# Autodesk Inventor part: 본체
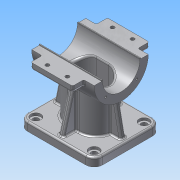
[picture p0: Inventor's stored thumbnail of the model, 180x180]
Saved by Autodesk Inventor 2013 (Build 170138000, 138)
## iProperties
Created: 2015-12
Part Number: 본체
Material: 알루미늄 6061
Document SubType Name: Modeling
Designer: mduedu
Density: 2.71 g/cm^3
Mass: 475.397 g
Surface Area: 479.254 cm^2
Volume: 175.423 cm^3
Author: mduedu
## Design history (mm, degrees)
sketch "스케치1"
  geometry: L1 (45, 40)-(-45, 40); L2 (-45, 40)-(-45, -40); L3 (-45, -40)-(45, -40); L4 (45, -40)-(45, 40); L5 (45, 40)-(-45, -40); L6 (-45, 40)-(45, -40); 1 further point
  constraints: 12 end point, 2 midpoint, 2 parallel, 1 horizontal, 1 perpendicular
  dimensions: "d0" = 90 distance of L2.end L3.end; "d2" = 80 distance of L1.end L2.end
extrude "돌출1" new body sketch "스케치1" distance "d3" = 10; taper "d4" = 0 deg
sketch "스케치2"
  geometry: L1 (0, 40)-(0, -40) reference; C1 r 32.5 at (80, 0); 1 further point
  constraints: 1 centre point
  dimensions: "d5" = 65 diameter of C1; "d6" = 80 distance from line of C1.centre L1
extrude "돌출2" join sketch "스케치2" stored distance "d7" = 75; taper "d8" = 0 deg
sketch "스케치3"
  geometry: L1 (-27.5, -20)-(27.5, -20); L2 (27.5, -20)-(27.5, 20); L3 (27.5, 20)-(-27.5, 20); L4 (-27.5, 20)-(-27.5, -20); L5 (-27.5, -20)-(27.5, 20); L6 (27.5, -20)-(-27.5, 20); 1 further point
  constraints: 12 end point, 2 midpoint, 2 parallel, 1 horizontal, 1 perpendicular
  dimensions: "d9" = 55 distance of L2.end L3.end; "d11" = 40 distance of L1.end L2.end
extrude "돌출3" new body sketch "스케치3" stored distance "d12" = 75; taper "d13" = 0 deg
fillet "모깎기1"
fillet "모깎기2"
feature "결합1"
  node "솔리드2"
fillet "모깎기3" dims "d14" = 10
sketch "스케치4"
  geometry: L1 (-37.5, 47.5)-(37.5, 47.5) reference; L2 (35, 10)-(45, 10) reference; L3 (32.5, 47.5)-(40, 10); L4 (37.5, 47.5)-(37.5, 112.5) reference; L5 (45, 10)-(45, 0) reference; 1 further point
  constraints: 2 end point, 1 midpoint, 1 point on line
  dimensions: "d15" = 5 distance from line of L3.start L4; "d16" = 5 distance from line of L3.end L5
sketch "스케치5"
  geometry: L1 (10, 40)-(10, 30) reference; L2 (10, 35)-(56.569, 22.522); L3 (0, 40)-(10, 40) reference; 2 further points
  constraints: 2 end point, 1 midpoint, 2 other
  dimensions: "d17" = 5 distance from line of L2.start L3; "d18" = 15 deg angle of L2 L3
feature "리브1" dims "d19" = 1, "d20" = 6, "d21" = 0, "d22" = 0, "d23" = 1, "d24" = 1
feature "리브2" dims "d25" = 1, "d26" = 6, "d27" = 0, "d28" = 0, "d29" = 1, "d30" = 1
fillet "모깎기4" dims "d31" = 2
fillet "모깎기5" dims "d32" = 2
fillet "모깎기6" dims "d33" = 2
sketch "스케치6"
  geometry: A1 r 10 centre (-35, 30) between (-35, 40) and (-45, 30) reference; A2 r 10 centre (35, 30) between (45, 30) and (35, 40) reference; A3 r 10 centre (35, -30) between (35, -40) and (45, -30) reference; A4 r 10 centre (-35, -30) between (-45, -30) and (-35, -40) reference; 5 further points
  constraints: 4 coincident
hole "구멍1" sketch "스케치6" at (-35, 30), (35, 30), (35, -30), (-35, -30) diameter "d34" = 7; stored, may be unused: countersink angle "d38" = 90 deg, drill point angle "d40" = 118 deg; dims "d35" = 6, "d36" = 12, "d37" = 3, "d39" = 8
fillet "모깎기7" dims "d41" = 2
hole "구멍2" diameter "d44" = 45; stored, may be unused: countersink angle "d48" = 90 deg, drill point angle "d50" = 118 deg; dims "d42" = 10, "d43" = 10, "d45" = 6, "d46" = 4, "d47" = 2, "d49" = 8
sketch "스케치7" dims "d52" = 26.5
  geometry: L1 (0, 0)-(32.5, 0); L2 (0, 0)-(22.981, 22.981); A1 r 32.5 centre (0, 0) between (32.5, 0) and (22.981, 22.981) reference; 3 further points
  constraints: 4 end point, 2 point on circle, 1 coincident, 1 horizontal, 1 point on line, 3 other
  dimensions: "d51" = 45 deg angle of L2 L1
hole "구멍3" sketch "스케치7" at (18.738, 18.738) diameter "d54" = 2.459; stored, may be unused: countersink angle "d58" = 90 deg, drill point angle "d60" = 118 deg; dims "d55" = 8, "d56" = 4, "d57" = 2, "d59" = 10
sketch "스케치8"
  geometry: L1 (72.5, 31.623)-(72.5, 46); L2 (72.5, 46)-(87.5, 46); L3 (87.5, 46)-(87.5, 31.623); A1 r 32.5 centre (80, 0) between (87.5, 31.623) and (72.5, 31.623) reference; 2 further points
  constraints: 6 end point, 2 point on circle, 1 midpoint, 1 parallel, 1 vertical, 1 vertical alignment
  dimensions: "d64" = 15 distance of L1.end L2.end; "d66" = 46 distance from line of L2 A1.centre
extrude "돌출4" join sketch "스케치8" stored distance "d67" = 50; taper "d68" = 0 deg
fillet "모깎기8" dims "d69" = 3
fillet "모깎기9" dims "d70" = 2
sketch "스케치9"
  geometry: L1 (-76, 82.5)-(76, 82.5); L2 (76, 82.5)-(76, 0); L3 (76, 0)-(-76, 0); L4 (-76, 0)-(-76, 82.5); L5 (-46, 4.5)-(-46, -4.5) reference; C1 r 32.5 at (0, 0) reference; 2 further points
  constraints: 8 end point, 2 parallel, 1 coincident, 1 horizontal, 1 midpoint, 1 perpendicular
  dimensions: "d71" = 50 distance edge to line of C1 L1; "d72" = 30 distance between parallel lines of L4 L5
extrude "돌출5" cut sketch "스케치9" stored distance "d73" = 0; taper "d74" = 0 deg
node "작업 평면1"
sketch "스케치10"
  geometry: L1 (-7.5, 15)-(7.5, 15); L2 (-7.5, -15)-(7.5, -15); A1 r 20 centre (-7.5, 0) between (-7.5, 20) and (-26.977, 4.545) reference; A2 r 20 centre (7.5, 0) between (26.977, 4.545) and (7.5, 20) reference; A3 r 15 centre (-7.5, 0) between (-7.5, 15) and (-7.5, -15); A4 r 15 centre (7.5, 0) between (7.5, -15) and (7.5, 15); 1 further point
  constraints: 7 point on circle, 4 end point, 4 tangent, 3 point on line, 2 centre point, 2 coincident, 1 horizontal
  dimensions: "d77" = 5 radial gap between concentric circles of A3 A1
extrude "돌출6" cut sketch "스케치10" stored distance "d78" = 50; taper "d79" = 0 deg
fillet "모깎기10" dims "d80" = 3
sketch "스케치11"
  geometry: 2 further points
  constraints: 1 coincident
hole "구멍4" sketch "스케치11" at (0, 0) diameter "d81" = 12; stored, may be unused: countersink angle "d85" = 90 deg, drill point angle "d87" = 118 deg; dims "d82" = 8, "d83" = 40, "d84" = 10, "d86" = 10
sketch "스케치12"
  geometry: C1 r 10 at (0, 0); 1 further point
  constraints: 1 centre point, 1 coincident
  dimensions: "d88" = 20 diameter of C1
extrude "돌출7" cut sketch "스케치12" distance "d89" = 5; taper "d90" = 0 deg
chamfer "모따기1" distance "d91" = 1; stored, may be unused: second distance "d92" = 2, angle "d93" = 45 deg
fillet "모깎기11" dims "d94" = 0.5
feature "립1" dims "d95" = 1, "d96" = 1, "d97" = 0, "d98" = 3 deg, "d99" = 3 deg, "d100" = 0
sketch "스케치13"
  geometry: 4 further points
hole "구멍5" sketch "스케치13" at (34, 5.936), (10, -72.269), (34, -72.269), (10, 5.936) diameter "d101" = 4.5; stored, may be unused: countersink angle "d105" = 90 deg, drill point angle "d107" = 0 deg; dims "d102" = 6, "d103" = 4, "d104" = 2, "d106" = 8
fillet "모깎기12" dims "d115" = 0.3
node "솔리드1"
mirror "대칭1"
mirror "대칭2"
pattern_circular "원형 패턴1" dims angle "d62" = 360 deg
mirror "대칭3"
mirror "대칭4"
